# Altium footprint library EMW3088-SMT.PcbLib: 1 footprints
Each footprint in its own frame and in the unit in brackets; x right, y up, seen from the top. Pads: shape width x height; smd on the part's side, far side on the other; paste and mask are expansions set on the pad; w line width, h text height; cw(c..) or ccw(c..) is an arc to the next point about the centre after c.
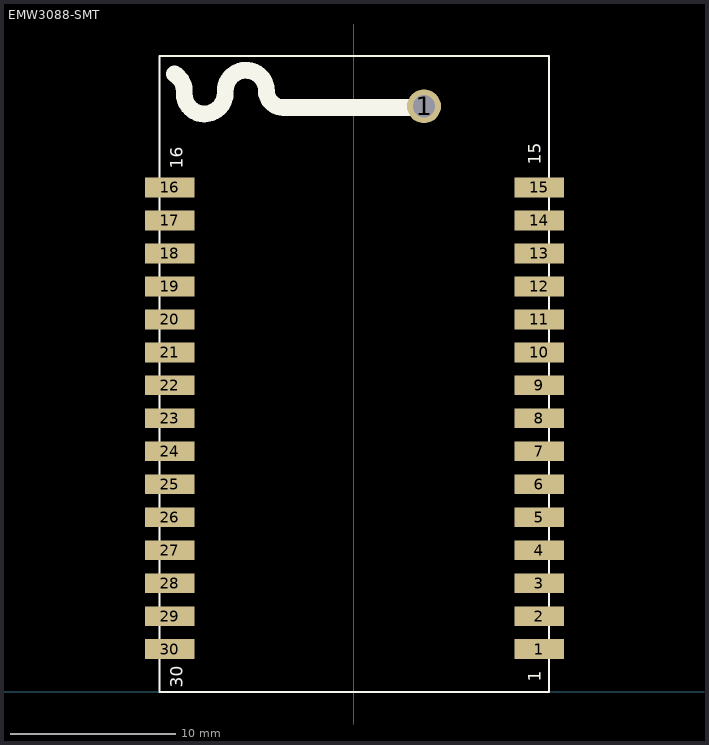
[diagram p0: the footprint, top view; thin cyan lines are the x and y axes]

## EMW3088-SMT [mm]
pads (31):
  round 2.057 hole 1.346: 1(4.266,35.517)
  rect 3x1.2 smd: 1(11.251,2.589) 2(11.251,4.589) 3(11.251,6.589) 4(11.251,8.589) 5(11.251,10.59) 6(11.251,12.589) 7(11.251,14.589) 8(11.251,16.589) 9(11.251,18.589) 10(11.251,20.589) 11(11.251,22.59) 12(11.251,24.59) 13(11.251,26.589) 14(11.251,28.59) 15(11.251,30.589) 16(-11.149,30.589) 17(-11.149,28.59) 18(-11.149,26.589) 19(-11.149,24.59) 20(-11.149,22.59) 21(-11.149,20.589) 22(-11.149,18.59) 23(-11.149,16.589) 24(-11.149,14.59) 25(-11.149,12.589) 26(-11.149,10.59) 27(-11.149,8.589) 28(-11.149,6.589) 29(-11.149,4.589) 30(-11.149,2.589)
Top Layer:
  lines w0.508: 10.235,30.613 10.244,30.622 10.616,30.622
Top Overlay:
  lines w0.127: -11.774,-0.022 -11.774,38.576 11.848,38.576 11.848,-0.022 -11.774,-0.022
  lines w1.016: -10.869,37.479 cw(c-11.492,36.431) -10.273,36.431 -10.273,36.255 ccw(c-9.07,36.255) -9.916,35.401 ccw(c-9.07,36.255) -9.07,35.052 ccw(c-9.07,36.339) -8.456,35.208 ccw(c-9.07,36.339) -7.783,36.339 -7.783,36.457 cw(c-6.539,36.457) -7.39,37.365 cw(c-6.539,36.457) -6.217,37.659 cw(c-6.539,36.456) -5.474,37.101 cw(c-6.539,36.457) -5.294,36.457 ccw(c-4.278,36.457) -4.278,35.441 4.19,35.441
  text "1" at 11.34,0.613 h0.76
  text "15" at 11.34,31.982 h0.76
  text "16" at -10.377,31.728 h0.76
  text "30" at -10.377,0.232 h0.76
3D body "User Library-MM8430-2610.STEP": height 2.75, standoff 1, extent 3.517,29.806 6.517,32.806
3D body: height 1.2, standoff 0, extent 10.532,6.298 11.131,6.898
3D body: height 1.2, standoff 0, extent 10.532,4.298 11.131,4.898
3D body: height 1.2, standoff 0, extent 10.532,2.298 11.131,2.898
3D body: height 1.2, standoff 0, extent 10.532,14.298 11.131,14.898
3D body: height 1.2, standoff 0, extent 10.532,12.298 11.131,12.898
3D body: height 1.2, standoff 0, extent 10.532,8.298 11.131,8.898
3D body: height 1.2, standoff 0, extent 10.532,10.298 11.131,10.898
3D body: height 1.2, standoff 0, extent 10.532,22.298 11.131,22.898
3D body: height 1.2, standoff 0, extent 10.532,20.298 11.131,20.898
3D body: height 1.2, standoff 0, extent 10.532,16.298 11.131,16.898
3D body: height 1.2, standoff 0, extent 10.532,18.298 11.131,18.898
3D body: height 1.2, standoff 0, extent 10.532,30.298 11.131,30.898
3D body: height 1.2, standoff 0, extent 10.532,28.298 11.131,28.898
3D body: height 1.2, standoff 0, extent 10.532,24.298 11.131,24.898
3D body: height 1.2, standoff 0, extent 10.532,26.298 11.131,26.898
3D body: height 1.2, standoff 0, extent -11.068,6.298 -10.469,6.898
3D body: height 1.2, standoff 0, extent -11.068,4.298 -10.469,4.898
3D body: height 1.2, standoff 0, extent -11.068,2.298 -10.469,2.898
3D body: height 1.2, standoff 0, extent -11.068,14.298 -10.469,14.898
3D body: height 1.2, standoff 0, extent -11.068,12.298 -10.469,12.898
3D body: height 1.2, standoff 0, extent -11.068,8.298 -10.469,8.898
3D body: height 1.2, standoff 0, extent -11.068,10.298 -10.469,10.898
3D body: height 1.2, standoff 0, extent -11.068,22.298 -10.469,22.898
3D body: height 1.2, standoff 0, extent -11.068,20.298 -10.469,20.898
3D body: height 1.2, standoff 0, extent -11.068,16.298 -10.469,16.898
3D body: height 1.2, standoff 0, extent -11.068,18.298 -10.469,18.898
3D body: height 1.2, standoff 0, extent -11.068,26.298 -10.469,26.898
3D body: height 1.2, standoff 0, extent -11.068,24.298 -10.469,24.898
3D body: height 1.2, standoff 0, extent -11.068,28.298 -10.469,28.898
3D body: height 1, standoff 0, extent -11.069,30.299 -10.469,30.898
3D body: height 1, standoff 0, extent -11.798,0 11.824,38.583
3D body: height 1, standoff 0, extent -11.798,29.997 -10.169,31.198
3D body: height 1, standoff 0, extent -11.798,28.003 -10.169,29.204
3D body: height 1, standoff 0, extent -11.798,24.003 -10.169,25.203
3D body: height 1, standoff 0, extent -11.798,25.997 -10.169,27.197
3D body: height 1, standoff 0, extent -11.798,17.996 -10.169,19.196
3D body: height 1, standoff 0, extent -11.798,15.989 -10.169,17.19
3D body: height 1, standoff 0, extent -11.798,20.002 -10.169,21.203
3D body: height 1, standoff 0, extent -11.798,21.996 -10.169,23.197
3D body: height 1, standoff 0, extent -11.798,9.995 -10.169,11.189
3D body: height 1, standoff 0, extent -11.798,8.001 -10.169,9.195
3D body: height 1, standoff 0, extent -11.798,12.002 -10.169,13.195
3D body: height 1, standoff 0, extent -11.798,13.995 -10.169,15.196
3D body: height 1, standoff 0, extent -11.798,1.994 -10.169,3.188
3D body: height 1, standoff 0, extent -11.798,4 -10.169,5.194
3D body: height 1, standoff 0, extent -11.798,5.994 -10.169,7.188
3D body: height 1, standoff 0, extent 10.211,5.994 11.84,7.188
3D body: height 1, standoff 0, extent 10.211,4 11.84,5.194
3D body: height 1, standoff 0, extent 10.211,1.981 11.84,3.175
3D body: height 1, standoff 0, extent 10.211,13.995 11.84,15.189
3D body: height 1, standoff 0, extent 10.211,12.002 11.84,13.195
3D body: height 1, standoff 0, extent 10.211,7.988 11.84,9.182
3D body: height 1, standoff 0, extent 10.211,9.982 11.84,11.176
3D body: height 1, standoff 0, extent 10.211,21.996 11.84,23.19
3D body: height 1, standoff 0, extent 10.211,20.002 11.84,21.196
3D body: height 1, standoff 0, extent 10.211,15.989 11.84,17.183
3D body: height 1, standoff 0, extent 10.211,17.996 11.84,19.19
3D body: height 1, standoff 0, extent 10.211,25.997 11.84,27.191
3D body: height 1, standoff 0, extent 10.211,24.003 11.84,25.197
3D body: height 1, standoff 0, extent 10.211,28.003 11.84,29.197
3D body: height 1, standoff 0, extent 10.211,29.997 11.84,31.191
3D body: height 1, standoff 0.01, extent 11.358,26.132 11.849,27.133
3D body: height 1, standoff 0.01, extent 11.358,28.132 11.849,29.133
3D body: height 1, standoff 0.01, extent 11.358,30.132 11.849,31.133
3D body: height 1, standoff 0.01, extent 11.358,14.132 11.849,15.133
3D body: height 1, standoff 0.01, extent 11.358,16.132 11.849,17.133
3D body: height 1, standoff 0.01, extent 11.358,20.132 11.849,21.133
3D body: height 1, standoff 0.01, extent 11.358,18.132 11.849,19.133
3D body: height 1, standoff 0.01, extent 11.358,24.132 11.849,25.133
3D body: height 1, standoff 0.01, extent 11.358,22.132 11.849,23.133
3D body: height 1, standoff 0.01, extent 11.358,2.132 11.849,3.133
3D body: height 1, standoff 0.01, extent 11.358,4.132 11.849,5.133
3D body: height 1, standoff 0.01, extent 11.358,8.132 11.849,9.133
3D body: height 1, standoff 0.01, extent 11.358,6.132 11.849,7.133
3D body: height 1, standoff 0.01, extent 11.358,12.132 11.849,13.133
3D body: height 1, standoff 0.01, extent 11.358,10.132 11.849,11.133
3D body: height 1, standoff 0.01, extent -11.798,6.107 -11.307,7.107
3D body: height 1, standoff 0.01, extent -11.798,4.106 -11.307,5.107
3D body: height 1, standoff 0.01, extent -11.798,2.107 -11.307,3.107
3D body: height 1, standoff 0.01, extent -11.798,18.107 -11.307,19.107
3D body: height 1, standoff 0.01, extent -11.798,16.106 -11.307,17.107
3D body: height 1, standoff 0.01, extent -11.798,12.106 -11.307,13.107
3D body: height 1, standoff 0.01, extent -11.798,14.107 -11.307,15.107
3D body: height 1, standoff 0.01, extent -11.798,8.106 -11.307,9.107
3D body: height 1, standoff 0.01, extent -11.798,10.107 -11.307,11.107
3D body: height 1, standoff 0.01, extent -11.798,30.107 -11.307,31.107
3D body: height 1, standoff 0.01, extent -11.798,28.106 -11.307,29.107
3D body: height 1, standoff 0.01, extent -11.798,24.106 -11.307,25.107
3D body: height 1, standoff 0.01, extent -11.798,26.107 -11.307,27.107
3D body: height 1, standoff 0.01, extent -11.798,20.106 -11.307,21.107
3D body: height 1, standoff 0.01, extent -11.798,22.107 -11.307,23.107
3D body "SW3dPS-U.FL-R-SMT-1.STEP": height 2.45, standoff 1.19, extent 8.228,34.531 11.228,37.631
3D body: height 3.7, standoff 1, extent -9.499,1.262 9.401,28.812
3D body: height 0.1, standoff 0, extent -4.811,34.958 -3.796,35.974
3D body: height 0.1, standoff 0, extent -5.746,35.594 -4.731,36.61
3D body: height 0.1, standoff 0, extent -5.677,35.464 -4.661,36.48
3D body: height 0.1, standoff 0, extent -5.546,35.274 -4.531,36.29
3D body: height 0.1, standoff 0, extent -5.446,35.184 -4.431,36.2
3D body: height 0.1, standoff 0, extent -5.287,35.094 -4.271,36.11
3D body: height 0.1, standoff 0, extent -5.146,35.034 -4.131,36.05
3D body: height 0.1, standoff 0, extent -5.017,34.974 -4.001,35.99
3D body: height 0.1, standoff 0, extent -5.816,35.814 -4.801,36.83
3D body: height 0.1, standoff 0, extent -5.827,35.974 -4.812,36.99
3D body: height 0.1, standoff 0, extent -5.826,36.114 -4.811,37.13
3D body: height 0.1, standoff 0, extent -5.846,36.224 -4.831,37.24
3D body: height 0.1, standoff 0, extent -5.856,36.294 -4.841,37.31
3D body: height 0.1, standoff 0, extent -5.907,36.444 -4.891,37.46
3D body: height 0.1, standoff 0, extent -6.007,36.619 -4.991,37.634
3D body: height 0.1, standoff 0, extent -6.116,36.764 -5.101,37.78
3D body: height 0.1, standoff 0, extent -6.216,36.874 -5.201,37.89
3D body: height 0.1, standoff 0, extent -6.287,36.944 -5.271,37.96
3D body: height 0.1, standoff 0, extent -6.337,36.974 -5.321,37.99
3D body: height 0.1, standoff 0, extent -6.406,37.024 -5.391,38.04
3D body: height 0.1, standoff 0, extent -6.426,37.044 -5.411,38.06
3D body: height 0.1, standoff 0, extent -6.547,37.104 -5.531,38.12
3D body: height 1.01, standoff 0, extent -6.647,37.144 -5.631,38.16
3D body: height 0.1, standoff 0, extent -6.776,37.184 -5.761,38.2
3D body: height 0.1, standoff 0, extent -6.927,37.204 -5.911,38.22
3D body: height 0.1, standoff 0, extent -7.076,37.214 -6.061,38.23
3D body: height 0.1, standoff 0, extent -7.207,37.204 -6.191,38.22
3D body: height 0.1, standoff 0, extent -7.317,37.184 -6.301,38.2
3D body: height 0.1, standoff 0, extent -7.507,37.124 -6.491,38.14
3D body: height 0.1, standoff 0, extent -7.696,37.044 -6.681,38.06
3D body: height 0.1, standoff 0, extent -7.837,36.944 -6.821,37.96
3D body: height 0.1, standoff 0, extent -7.966,36.824 -6.951,37.84
3D body: height 0.1, standoff 0, extent -8.066,36.704 -7.051,37.72
3D body: height 0.1, standoff 0, extent -8.147,36.594 -7.131,37.61
3D body: height 0.1, standoff 0, extent -8.207,36.474 -7.191,37.49
3D body: height 0.1, standoff 0, extent -8.267,36.324 -7.251,37.34
3D body: height 0.1, standoff 0, extent -8.296,36.154 -7.281,37.17
3D body: height 0.1, standoff 0, extent -8.306,36.034 -7.291,37.05
3D body: height 0.1, standoff 0, extent -8.306,35.904 -7.291,36.92
3D body: height 0.1, standoff 0, extent -8.316,35.714 -7.301,36.73
3D body: height 0.1, standoff 0, extent -8.346,35.544 -7.331,36.56
3D body: height 0.1, standoff 0, extent -8.386,35.414 -7.371,36.43
3D body: height 0.1, standoff 0, extent -8.436,35.304 -7.421,36.32
3D body: height 0.1, standoff 0, extent -8.527,35.134 -7.511,36.15
3D body: height 0.1, standoff 0, extent -8.636,35.004 -7.621,36.02
3D body: height 0.1, standoff 0, extent -8.756,34.884 -7.741,35.9
3D body: height 0.1, standoff 0, extent -8.877,34.794 -7.861,35.81
3D body: height 0.1, standoff 0, extent -8.996,34.724 -7.981,35.74
3D body: height 0.1, standoff 0, extent -9.127,34.664 -8.111,35.68
3D body: height 0.1, standoff 0, extent -9.286,34.614 -8.271,35.63
3D body: height 0.1, standoff 0, extent -9.406,34.594 -8.391,35.61
3D body: height 0.1, standoff 0, extent -9.497,34.584 -8.481,35.6
3D body: height 0.1, standoff 0, extent -9.636,34.584 -8.621,35.6
3D body: height 0.1, standoff 0, extent -9.747,34.584 -8.731,35.6
3D body: height 0.1, standoff 0, extent -9.876,34.614 -8.861,35.63
3D body: height 0.1, standoff 0, extent -10.006,34.654 -8.991,35.67
3D body: height 0.1, standoff 0, extent -10.186,34.734 -9.171,35.75
3D body: height 0.1, standoff 0, extent -10.316,34.824 -9.301,35.84
3D body: height 0.1, standoff 0, extent -10.506,34.984 -9.491,36
3D body: height 0.1, standoff 0, extent -10.596,35.104 -9.581,36.12
3D body: height 0.1, standoff 0, extent -10.677,35.254 -9.661,36.27
3D body: height 0.1, standoff 0, extent -10.737,35.374 -9.721,36.39
3D body: height 0.1, standoff 0, extent -10.767,35.484 -9.751,36.5
3D body: height 0.1, standoff 0, extent -10.787,35.614 -9.771,36.63
3D body: height 0.1, standoff 0, extent -10.797,35.724 -9.781,36.74
3D body: height 0.1, standoff 0, extent -10.797,35.864 -9.781,36.88
3D body: height 0.1, standoff 0, extent -10.797,36.034 -9.781,37.05
3D body: height 0.1, standoff 0, extent -10.816,36.114 -9.801,37.13
3D body: height 0.1, standoff 0, extent -10.836,36.234 -9.821,37.25
3D body: height 0.1, standoff 0, extent -10.876,36.384 -9.861,37.4
3D body: height 0.1, standoff 0, extent -10.926,36.484 -9.911,37.5
3D body: height 0.1, standoff 0, extent -10.976,36.574 -9.961,37.59
3D body: height 0.1, standoff 0, extent -11.047,36.684 -10.031,37.7
3D body: height 0.1, standoff 0, extent -11.387,36.984 -10.371,38
3D body: height 0.1, standoff 0, extent -11.256,36.894 -10.241,37.91
3D body: height 0.1, standoff 0, extent -11.156,36.804 -10.141,37.82
3D body: height 1, standoff 0, extent -4.434,34.954 4.191,35.97
3D body: height 1, standoff 0, extent 3.594,34.844 4.94,36.19
3D body: height 1, standoff 0, extent 3.241,34.49 5.294,36.544
3D body: height 0.99, standoff 0, extent -11.799,32.972 5.351,38.583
